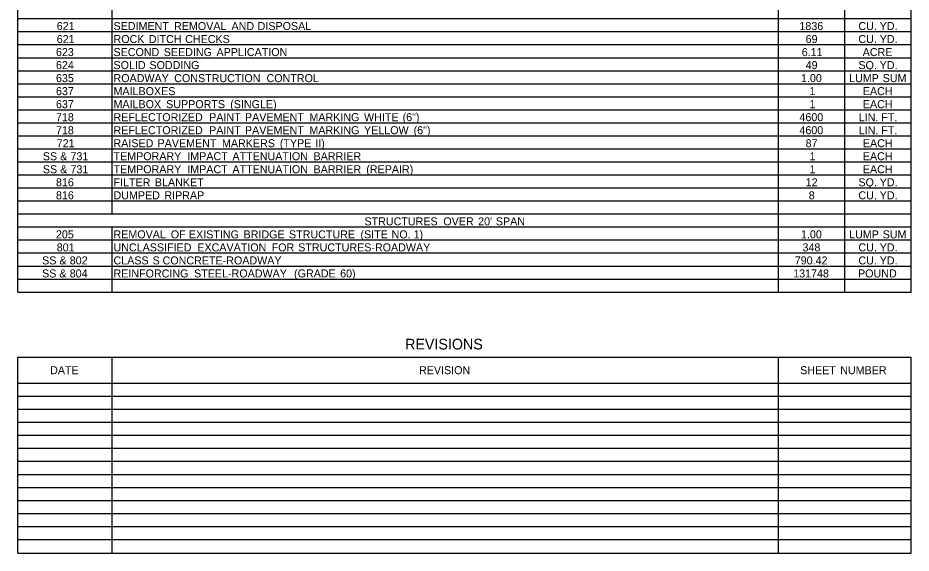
# Model space of a CAD drawing. Extents: x 1940653 to 1945779, y 534266 to 535271.
# Drawn here: x 1944649 to 1945251, y 534456 to 534817 of the extents above; entities that cross this region are included whole.
import ezdxf

# ---------------------------------------------------------------- set-up
doc = ezdxf.new("R2010")
doc.units = 0
doc.layers.add('Default', color=7, linetype='Continuous')

msp = doc.modelspace()

# ---------------------------------------------------------------- linework, layer by layer
at = {"layer": 'Default'}
for p, q in [((1944648.86, 534632.28), (1944648.86, 535167.56)), ((1944648.86, 534632.28), (1944648.86, 535167.56)), ((1944712.48, 534684.93), (1944712.48, 535167.56)), ((1945161.76, 534632.28), (1945161.76, 535167.56)), ((1945206.51, 534632.28), (1945206.51, 535167.56)), ((1945206.51, 534684.93), (1945206.51, 535167.56)), ((1945251.26, 534632.28), (1945251.26, 535167.56)), ((1944712.48, 534684.93), (1944712.48, 535141.23)), ((1945161.76, 534684.93), (1945161.76, 535141.23)), ((1944648.86, 534816.56), (1945251.26, 534816.56)), ((1944648.86, 534807.78), (1945251.26, 534807.78)), ((1944648.86, 534799.01), (1945251.26, 534799.01)), ((1944648.86, 534790.23), (1945251.26, 534790.23)), ((1944648.86, 534781.46), (1945251.26, 534781.46)), ((1944648.86, 534772.68), (1945251.26, 534772.68)), ((1944648.86, 534763.91), (1945251.26, 534763.91)), ((1944648.86, 534755.13), (1945251.26, 534755.13)), ((1944648.86, 534746.36), (1945251.26, 534746.36)), ((1944648.86, 534737.58), (1945251.26, 534737.58)), ((1944648.86, 534728.81), (1945251.26, 534728.81)), ((1944648.86, 534720.03), (1945251.26, 534720.03)), ((1944648.86, 534711.26), (1945251.26, 534711.26)), ((1944648.86, 534702.48), (1945251.26, 534702.48)), ((1944648.86, 534693.71), (1945251.26, 534693.71)), ((1944648.86, 534684.93), (1945251.26, 534684.93)), ((1945206.51, 534684.93), (1945251.26, 534684.93)), ((1944648.86, 534676.16), (1945251.26, 534676.16)), ((1944712.48, 534632.28), (1944712.48, 534676.16)), ((1944712.48, 534632.28), (1944712.48, 534676.16)), ((1945161.76, 534632.28), (1945161.76, 534676.16)), ((1945206.51, 534632.28), (1945206.51, 534676.16)), ((1944648.86, 534667.38), (1945251.26, 534667.38)), ((1944648.86, 534658.61), (1945251.26, 534658.61)), ((1944648.86, 534649.83), (1945251.26, 534649.83)), ((1944648.86, 534641.06), (1945251.26, 534641.06)), ((1944648.86, 534632.28), (1945251.26, 534632.28)), ((1944648.86, 534588.41), (1945251.26, 534588.41)), ((1944648.86, 534588.41), (1944712.48, 534588.41)), ((1944648.86, 534456.35), (1944648.86, 534588.41)), ((1944648.86, 534456.35), (1944648.86, 534588.41)), ((1944712.48, 534456.35), (1944712.48, 534588.41)), ((1945161.76, 534588.41), (1945251.26, 534588.41)), ((1945161.76, 534570.86), (1945161.76, 534588.41)), ((1945161.76, 534456.35), (1945161.76, 534588.41)), ((1945251.26, 534456.35), (1945251.26, 534588.41)), ((1945251.26, 534456.35), (1945251.26, 534588.41)), ((1944648.86, 534570.86), (1945251.26, 534570.86)), ((1944648.86, 534562.08), (1945251.26, 534562.08)), ((1944648.86, 534553.31), (1945251.26, 534553.31)), ((1944648.86, 534544.53), (1945251.26, 534544.53)), ((1944648.86, 534535.76), (1945251.26, 534535.76)), ((1944648.86, 534526.98), (1945251.26, 534526.98)), ((1944648.86, 534518.21), (1945251.26, 534518.21)), ((1944648.86, 534509.43), (1945251.26, 534509.43)), ((1944648.86, 534500.66), (1945251.26, 534500.66)), ((1944648.86, 534491.88), (1945251.26, 534491.88)), ((1944648.86, 534483.11), (1945251.26, 534483.11)), ((1944648.86, 534474.33), (1945251.26, 534474.33)), ((1944648.86, 534465.56), (1945251.26, 534465.56)), ((1944648.86, 534456.35), (1945251.26, 534456.35))]:
    msp.add_line(p, q, dxfattribs=at)

# ---------------------------------------------------------------- texts
for s, height, p in [('621', 5.4, (1944675.07, 534808.86)), ('SEDIMENT', 5.4, (1944713.36, 534808.86)), (' REMOVAL', 5.4, (1944752.19, 534808.86)), (' AND', 5.4, (1944790.92, 534808.86)), (' DISPOSAL', 5.4, (1944808.54, 534808.86)), ('1836', 5.4, (1945175.92, 534808.86)), ('CU.', 5.4, (1945215.71, 534808.86)), (' YD.', 5.4, (1945228.05, 534808.86)), ('621', 5.4, (1944675.07, 534800.09)), ('ROCK', 5.4, (1944713.36, 534800.09)), (' DITCH', 5.4, (1944735.14, 534800.09)), (' CHECKS', 5.4, (1944759.68, 534800.09)), ('69', 5.4, (1945180.11, 534800.09)), ('CU.', 5.4, (1945215.71, 534800.09)), (' YD.', 5.4, (1945228.05, 534800.09)), ('623', 5.4, (1944674.55, 534791.31)), ('SECOND', 5.4, (1944713.36, 534791.31)), (' SEEDING', 5.4, (1944745.24, 534791.31)), (' APPLICATION', 5.4, (1944780.82, 534791.31)), ('6.11', 5.4, (1945177.49, 534791.31)), ('ACRE', 5.4, (1945218.61, 534791.31)), ('624', 5.4, (1944674.56, 534782.54)), ('SOLID', 5.4, (1944713.36, 534782.54)), (' SODDING', 5.4, (1944735.59, 534782.54)), ('49', 5.4, (1945180.11, 534782.54)), ('SQ.', 5.4, (1945215.71, 534782.54)), (' YD.', 5.4, (1945228.05, 534782.54)), ('635', 5.4, (1944674.53, 534773.76)), ('ROADWAY', 5.4, (1944713.36, 534773.76)), (' CONSTRUCTION', 5.4, (1944752.29, 534773.76)), (' CONTROL', 5.4, (1944814.55, 534773.76)), ('1.00', 5.4, (1945176.98, 534773.76)), ('LUMP', 5.4, (1945209.42, 534773.76)), (' SUM', 5.4, (1945230.06, 534773.76)), ('637', 5.4, (1944674.55, 534764.99)), ('MAILBOXES', 5.4, (1944713.36, 534764.99)), ('1', 5.4, (1945182.73, 534764.99)), ('EACH', 5.4, (1945218.71, 534764.99)), ('637', 5.4, (1944674.55, 534756.21)), ('MAILBOX', 5.4, (1944713.36, 534756.21)), (' SUPPORTS', 5.4, (1944746.85, 534756.21)), (' (SINGLE)', 5.4, (1944790.06, 534756.21)), ('1', 5.4, (1945182.73, 534756.21)), ('EACH', 5.4, (1945218.71, 534756.21)), ('718', 5.4, (1944674.55, 534747.44)), ('REFLECTORIZED', 5.4, (1944713.36, 534747.44)), (' PAINT', 5.4, (1944775.84, 534747.44)), (' PAVEMENT', 5.4, (1944800, 534747.44)), (' MARKING', 5.4, (1944843.46, 534747.44)), (' WHITE', 5.4, (1944880.3, 534747.44)), (' (6")', 5.4, (1944906.3, 534747.44)), ('4600', 5.4, (1945175.93, 534747.44)), ('LIN.', 5.4, (1945215.92, 534747.44)), (' FT.', 5.4, (1945229.1, 534747.44)), ('718', 5.4, (1944674.55, 534738.66)), ('REFLECTORIZED', 5.4, (1944713.36, 534738.66)), (' PAINT', 5.4, (1944775.84, 534738.66)), (' PAVEMENT', 5.4, (1944800, 534738.66)), (' MARKING', 5.4, (1944843.46, 534738.66)), (' YELLOW', 5.4, (1944880.3, 534738.66)), (' (6")', 5.4, (1944913.75, 534738.66)), ('4600', 5.4, (1945175.93, 534738.66)), ('LIN.', 5.4, (1945215.92, 534738.66)), (' FT.', 5.4, (1945229.1, 534738.66)), ('721', 5.4, (1944675.07, 534729.89)), ('RAISED', 5.4, (1944713.36, 534729.89)), (' PAVEMENT', 5.4, (1944741.05, 534729.89)), (' MARKERS', 5.4, (1944784.5, 534729.89)), (' (TYPE', 5.4, (1944823.52, 534729.89)), (' II)', 5.4, (1944847.43, 534729.89)), ('87', 5.4, (1945180.11, 534729.89)), ('EACH', 5.4, (1945218.71, 534729.89)), ('SS', 5.4, (1944665.71, 534721.11)), (' &', 5.4, (1944675.38, 534721.11)), (' 731', 5.4, (1944682.34, 534721.11)), ('TEMPORARY', 5.4, (1944713.36, 534721.11)), (' IMPACT', 5.4, (1944761.1, 534721.11)), (' ATTENUATION', 5.4, (1944791.55, 534721.11)), (' BARRIER', 5.4, (1944846.27, 534721.11)), ('1', 5.4, (1945182.73, 534721.11)), ('EACH', 5.4, (1945218.71, 534721.11)), ('SS', 5.4, (1944665.71, 534712.34)), (' &', 5.4, (1944675.38, 534712.34)), (' 731', 5.4, (1944682.34, 534712.34)), ('TEMPORARY', 5.4, (1944713.36, 534712.34)), (' IMPACT', 5.4, (1944761.1, 534712.34)), (' ATTENUATION', 5.4, (1944791.55, 534712.34)), (' BARRIER', 5.4, (1944846.27, 534712.34)), (' (REPAIR)', 5.4, (1944881.8, 534712.34)), ('1', 5.4, (1945182.73, 534712.34)), ('EACH', 5.4, (1945218.71, 534712.34)), ('816', 5.4, (1944674.55, 534703.56)), ('FILTER', 5.4, (1944713.36, 534703.56)), (' BLANKET', 5.4, (1944739.25, 534703.56)), ('12', 5.4, (1945180.14, 534703.56)), ('SQ.', 5.4, (1945215.71, 534703.56)), (' YD.', 5.4, (1945228.05, 534703.56)), ('816', 5.4, (1944674.55, 534694.79)), ('DUMPED', 5.4, (1944713.36, 534694.79)), (' RIPRAP', 5.4, (1944745.65, 534694.79)), ('8', 5.4, (1945182.21, 534694.79)), ('CU.', 5.4, (1945215.71, 534694.79)), (' YD.', 5.4, (1945228.05, 534694.79)), ('STRUCTURES', 5.4, (1944882.6, 534677.24)), (' OVER', 5.4, (1944933.79, 534677.24)), (" 20'", 5.4, (1944957.24, 534677.24)), (' SPAN', 5.4, (1944969.19, 534677.24)), ('205', 5.4, (1944674.53, 534668.46)), ('REMOVAL', 5.4, (1944713.36, 534668.46)), (' OF', 5.4, (1944749.99, 534668.46)), (' EXISTING', 5.4, (1944762.22, 534668.46)), (' BRIDGE', 5.4, (1944799.06, 534668.46)), (' STRUCTURE', 5.4, (1944829.68, 534668.46)), (' (SITE', 5.4, (1944877.9, 534668.46)), (' NO.', 5.4, (1944898.88, 534668.46)), (' 1)', 5.4, (1944913.73, 534668.46)), ('1.00', 5.4, (1945176.98, 534668.46)), ('LUMP', 5.4, (1945209.42, 534668.46)), (' SUM', 5.4, (1945230.06, 534668.46)), ('801', 5.4, (1944675.07, 534659.69)), ('UNCLASSIFIED', 5.4, (1944713.36, 534659.69)), (' EXCAVATION', 5.4, (1944767.88, 534659.69)), (' FOR', 5.4, (1944818, 534659.69)), (' STRUCTURES-ROADWAY', 5.4, (1944835.92, 534659.69)), ('348', 5.4, (1945178.01, 534659.69)), ('CU.', 5.4, (1945215.71, 534659.69)), (' YD.', 5.4, (1945228.05, 534659.69)), ('SS', 5.4, (1944665.22, 534650.91)), (' &', 5.4, (1944674.89, 534650.91)), (' 802', 5.4, (1944681.84, 534650.91)), ('CLASS', 5.4, (1944713.36, 534650.91)), (' S', 5.4, (1944737.71, 534650.91)), (' CONCRETE-ROADWAY', 5.4, (1944744.44, 534650.91)), ('790.42', 5.4, (1945172.8, 534650.91)), ('CU.', 5.4, (1945215.71, 534650.91)), (' YD.', 5.4, (1945228.05, 534650.91)), ('SS', 5.4, (1944665.2, 534642.14)), (' &', 5.4, (1944674.87, 534642.14)), (' 804', 5.4, (1944681.83, 534642.14)), ('REINFORCING', 5.4, (1944713.36, 534642.14)), (' STEEL-ROADWAY', 5.4, (1944765.7, 534642.14)), (' (GRADE', 5.4, (1944833.14, 534642.14)), (' 60)', 5.4, (1944864.18, 534642.14)), ('131748', 5.4, (1945171.72, 534642.14)), ('POUND', 5.4, (1945215.46, 534642.14)), ('REVISIONS', 7.2, (1944909.97, 534593.58)), ('DATE', 5.4, (1944670.59, 534576.93)), ('REVISION', 5.4, (1944919.39, 534576.93)), ('SHEET', 5.4, (1945176.42, 534576.93)), (' NUMBER', 5.4, (1945201.43, 534576.93))]:
    msp.add_text(s, height=height, dxfattribs=at).set_placement(p)

doc.saveas('drawing.dxf')
